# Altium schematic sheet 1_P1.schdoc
size 429 x 307 mm; Symbol: Sheet-Symbol_A3; Device: Sheet-Symbol_A3; Company: 嘉立创EDA; Version: V1.0; Page Size: A3; @Project Name: CASA0021; @Page Count: 1; @Update Date: 2025-02-10; @Create Date: 2025-02-08; @Schematic Name: 主控原理图_V0.2; @Page No: 1; @Page Name: P1; @Board Name: 核心板_V0.2; @Create Time: 18:02:16; @Update Time: 17:02:07; Width: 1655; Height: 1170; Region Start: 1; X Region Count: 6; Y Region Count: 4; Blade Width: 10; Title Block Position: 3
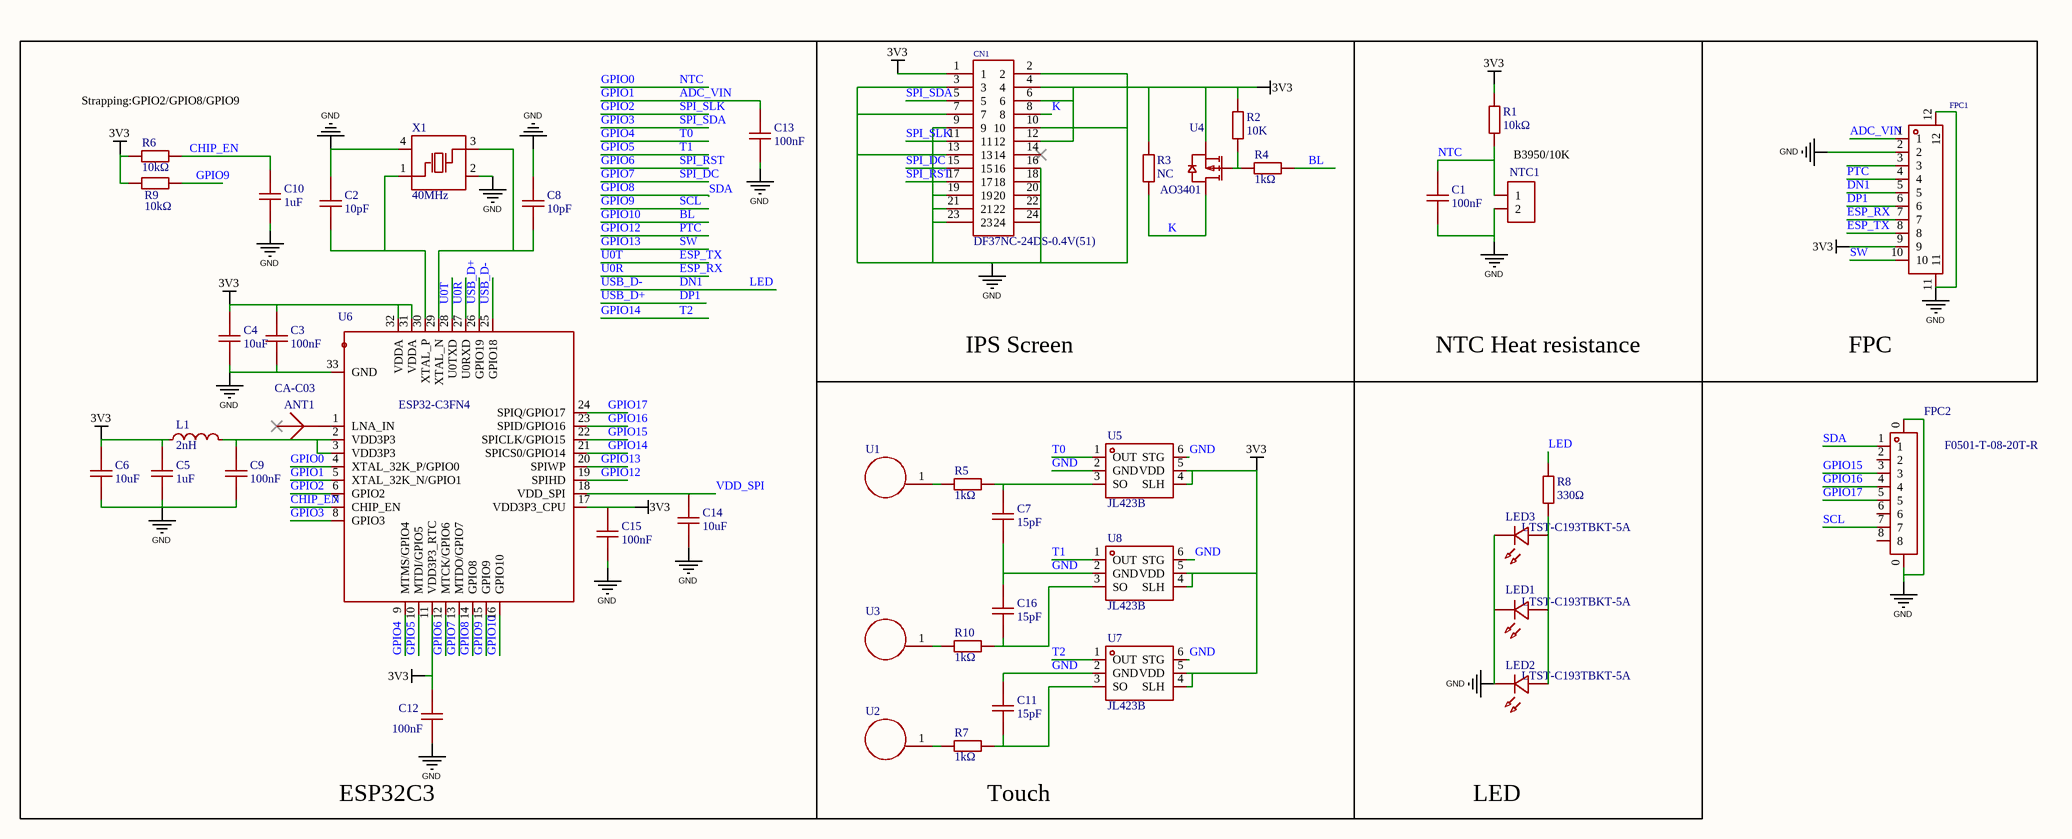
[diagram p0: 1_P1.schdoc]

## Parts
ANT1  CA-C03  [ANT-SMD_CA-C03]
C1  100nF  [C0603]
C2  10pF  [C0603]
C3  100nF  [C0603]
C4  10uF  [C0603]
C5  1uF  [C0603]
C6  10uF  [C0603]
C7  15pF  [C0603]
C8  10pF  [C0603]
C9  100nF  [C0603]
C10  1uF  [C0603]
C11  15pF  [C0603]
C12  100nF  [C0603]
C13  100nF  [C0603]
C14  10uF  [C0603]
C15  100nF  [C0603]
C16  15pF  [C0603]
CN1  DF37NC-24DS-0.4V(51)  [CONN-SMD_DF37NC-24DS-0.4V-51]
FPC1  F0501-T-10-20T-R  [FPC-SMD_F0501-T-10-20T-R]  (value not drawn)
FPC2  F0501-T-08-20T-R  [FPC-SMD_8P-P0.50_L4.4-W9.6]
L1  2nH  [L0603]
LED1  LTST-C193TBKT-5A  [LED0603-RD]
LED2  LTST-C193TBKT-5A  [LED0603-RD]
LED3  LTST-C193TBKT-5A  [LED0603-RD]
NTC1  (no value)  [HDR-TH_2P-P2.54-V-F]
R1  10kΩ  [R0603]
R2  10K  [R0603]
R3  NC  [R0603]
R4  1kΩ  [R0603]
R5  1kΩ  [R0603]
R6  10kΩ  [R0603]
R7  1kΩ  [R0603]
R8  330Ω  [R0603]
R9  10kΩ  [R0603]
R10  1kΩ  [R0603]
U1  F10-10-6.5-0.4P  [TH_F10-10-6.5-0.4P]  (value not drawn)
U2  F10-10-6.5-0.4P  [TH_F10-10-6.5-0.4P]  (value not drawn)
U3  F10-10-6.5-0.4P  [TH_F10-10-6.5-0.4P]  (value not drawn)
U4  AO3401  [SOT-23-3_L2.9-W1.3-P1.90-LS2.4-BR]
U5  JL423B  [SOT-23-6_L2.9-W1.6-P0.95-LS2.8-BL-2]
U6  ESP32-C3FN4  [QFN-32_L5.0-W5.0-P0.50-BL-EP3.7]
U7  JL423B  [SOT-23-6_L2.9-W1.6-P0.95-LS2.8-BL-2]
U8  JL423B  [SOT-23-6_L2.9-W1.6-P0.95-LS2.8-BL-2]
X1  40MHz  [OSC-SMD_4P-L3.2-W2.5-BL_SIT8008BI]

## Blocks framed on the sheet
ESP32C3: ANT1 C2-C6 C8-C10 C12-C15 L1 R6 R9 U6 X1
IPS Screen: CN1 R2-R4 U4
NTC Heat resistance: C1 NTC1 R1
FPC: FPC1
Touch: C7 C11 C16 R5 R7 R10 U1-U3 U5 U7 U8
LED: LED1-LED3 R8

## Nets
3V3: C3.2 C4.2 C5.2 C6.2 C12.2 C15.2 CN1.1 CN1.4 CN1.6 CN1.12 FPC1.9 L1.1 R1.2 R2.1 R3.1 R6.1 R9.1 U4.2(S) U5.4(SLH) U5.5(VDD) U6.11(VDD3P3_RTC) U6.17(VDD3P3_CPU) U6.31(VDDA) U6.32(VDDA) U7.4(SLH) U7.5(VDD) U8.4(SLH) U8.5(VDD)
GND: C1.1 C2.2 C3.1 C4.1 C5.1 C6.1 C7.1 C8.2 C9.1 C10.1 C11.2 C12.1 C13.2 C14.1 C15.1 C16.2 CN1.2 CN1.3 CN1.7 CN1.9 CN1.10 CN1.13 CN1.16 CN1.18 CN1.19 CN1.20 CN1.21 CN1.22 CN1.23 CN1.24 FPC1.2 FPC1.11 FPC1.12 FPC2.0 LED1.1(C) LED2.1(C) LED3.1(C) NTC1.2 U5.2(GND) U5.6(STG) U6.33(GND) U7.2(GND) U7.6(STG) U8.2(GND) U8.6(STG) X1.2(GND) X1.4(GND)
ADC_VIN: C13.1 FPC1.1 U6.5(XTAL_32K_N/GPIO1)  [also labelled GPIO1]
BL: R4.1 U6.16(GPIO10)  [also labelled GPIO10]
CHIP_EN: C10.2 R6.2 U6.7(CHIP_EN)
DN1: FPC1.5 R8.1 U6.25(GPIO18)  [also labelled LED, USB_D-]
DP1: FPC1.6 U6.26(GPIO19)  [also labelled USB_D+]
ESP_RX: FPC1.7 U6.27(U0RXD)  [also labelled U0R]
ESP_TX: FPC1.8 U6.28(U0TXD)  [also labelled U0T]
GPIO0: C1.2 NTC1.1 R1.1 U6.4(XTAL_32K_P/GPIO0)  [also labelled NTC]
GPIO2: CN1.11 U6.6(GPIO2)  [also labelled SPI_SLK]
GPIO3: CN1.5 U6.8(GPIO3)  [also labelled SPI_SDA]
GPIO4: U5.1(OUT) U6.9(MTMS/GPIO4)  [also labelled T0]
GPIO5: U6.10(MTDI/GPIO5) U8.1(OUT)  [also labelled T1]
GPIO6: CN1.17 U6.12(MTCK/GPIO6)  [also labelled SPI_RST]
GPIO7: CN1.15 U6.13(MTDO/GPIO7)  [also labelled SPI_DC]
GPIO8: FPC2.1 U6.14(GPIO8)  [also labelled SDA]
GPIO9: FPC2.7 R9.2 U6.15(GPIO9)  [also labelled SCL]
GPIO12: FPC1.4 U6.19(SPIHD)  [also labelled PTC]
GPIO13: FPC1.10 U6.20(SPIWP)  [also labelled SW]
GPIO14: U6.21(SPICS0/GPIO14) U7.1(OUT)  [also labelled T2]
GPIO15: FPC2.3 U6.22(SPICLK/GPIO15)
GPIO16: FPC2.4 U6.23(SPID/GPIO16)
GPIO17: FPC2.5 U6.24(SPIQ/GPIO17)
K: CN1.8 R3.2 U4.3(D)
VDD_SPI: C14.2 U6.18(VDD_SPI)
NetANT1_2: ANT1.2(ANT) U6.1(LNA_IN)
NetC2_1: C2.1 U6.30(XTAL_P) X1.1(OSC1)
NetC7_2: C7.2 R5.2 U5.3(SO)
NetC8_1: C8.1 U6.29(XTAL_N) X1.3(OSC2)
NetC9_2: C9.2 L1.2 U6.2(VDD3P3) U6.3(VDD3P3)
NetC11_1: C11.1 R7.2 U7.3(SO)
NetC16_1: C16.1 R10.2 U8.3(SO)
NetLED1_2: LED1.2(A) LED2.2(A) LED3.2(A) R8.2
NetR2_2: R2.2 R4.2 U4.1(G)
NetR5_1: R5.1 U1.1
NetR7_1: R7.1 U2.1
NetR10_1: R10.1 U3.1

Not connected (* = marked no-connect by the designer): ANT1 1*; CN1 14*; FPC1 3; FPC2 2 6 8

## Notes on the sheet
- Strapping:GPIO2/GPIO8/GPIO9
- B3950/10K

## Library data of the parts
ANT1 = CA-C03: Add into BOM: yes
C1 C13 = CGA0603X7R104K500JT: Manufacturer: HRE(芯声); Symbol: CapAcitance; Add into BOM: yes; Tolerance: ±10%; Voltage Rated: 50V; Temperature Coefficient: X7R
C2 = CC0603KRNPO9BN100: Manufacturer: YAGEO(国巨); Symbol: CapAcitance; Add into BOM: yes; Tolerance: ±10%; Voltage Rated: 50V; Temperature Coefficient: NP0
C3 C9 C12 C15 = CC0603KRX7R9BB104: Manufacturer: YAGEO(国巨); Symbol: CapAcitance; Add into BOM: yes; Tolerance: ±10%; Voltage Rated: 50V; Temperature Coefficient: X7R
C4 C6 C14 = CL10A106KP8NNNC: Manufacturer: SAMSUNG(三星); Symbol: CapAcitance; Add into BOM: yes; Tolerance: ±10%; Voltage Rated: 10V; Temperature Coefficient: X5R
C5 C10 = CL10A105KA8NNNC: Manufacturer: SAMSUNG(三星); Symbol: CapAcitance; Add into BOM: yes; Tolerance: ±10%; Voltage Rated: 25V; Temperature Coefficient: X5R
C7 C11 C16 = CC0603JRNPO9BN150: Manufacturer: YAGEO(国巨); Symbol: CapAcitance; Add into BOM: yes; Tolerance: ±5%; Voltage Rated: 50V; Temperature Coefficient: NP0
C8 = CC0603FRNPO9BN100: Manufacturer: YAGEO(国巨); Symbol: CapAcitance; Add into BOM: yes; Tolerance: ±1%; Voltage Rated: 50V; Temperature Coefficient: NP0
CN1 = DF37NC-24DS-0.4V(51): Manufacturer: HRS(广濑); Add into BOM: yes; Pitch: 0.4mm; Gender: 母; Current Rating (Max): 300mA
FPC1 = F0501-T-10-20T-R: Manufacturer: XFCN(兴飞); Add into BOM: yes; Pitch: 0.5mm; Number of Contacts: 10P; Locking Feature: 抽屉式
FPC2 = F0501-T-08-20T-R: Manufacturer: XFCN(兴飞); Add into BOM: yes; Locking Feature: 抽屉式; Number of Contacts: 8P; Pitch: 0.5mm
L1 = SDCL1608C2N0STDF: Manufacturer: Sunlord(顺络); Symbol: SDCL1005C10NJTDFM01; Add into BOM: yes
LED1-LED3 = LTST-C193TBKT-5A: Manufacturer: LITEON(光宝); Symbol: LED_B; Convert to PCB: yes; Emitted Color: 蓝色; Forward Voltage (VF): 2.8V; Power Dissipation: 76mW; Forward Current: 5mA; Dominant Wavelength: 465nm~475nm; Peak Wavelength: 468nm; Lens Color: 无色透明透镜; Luminous Intensity: 15mcd; Viewing Angle: 130°
NTC1 = HDR-F_2.54_1x2P: Manufacturer: BOOMELE(博穆精密); Manufacturer Part: 2.54-1*2P母; Symbol: Header-Female-2.54_1x2; Convert to PCB: yes
R1 R6 R9 = 0603WAF1002T5E: Manufacturer: UNI-ROYAL(厚声); Symbol: 电阻; Add into BOM: yes; Tolerance: ±1%; Power(Watts): 100mW; Overload Voltage (Max): 75V; Temperature Coefficient: ±100ppm/℃
R2 R3 = Res_0402: Symbol: 电阻; Convert to PCB: yes; Add into BOM: no
R4 R5 R7 R10 = 0603WAF1001T5E: Manufacturer: UNI-ROYAL(厚声); Symbol: 电阻; Add into BOM: yes; Tolerance: ±1%; Power(Watts): 100mW; Overload Voltage (Max): 75V; Temperature Coefficient: ±100ppm/℃
R8 = 0603WAF3300T5E: Manufacturer: UNI-ROYAL(厚声); Symbol: 电阻; Add into BOM: yes; Tolerance: ±1%; Power(Watts): 100mW; Overload Voltage (Max): 75V; Temperature Coefficient: ±100ppm/℃
U1-U3 = F10-10-6.5-0.4P: Manufacturer: Sam&wing(芯网); Symbol: 触摸弹簧 H10.0MM; Add into BOM: yes
U4 = AO3401_1: Manufacturer: FOSAN(富信); Symbol: AO3401A_C5122001; Add into BOM: yes; Drain Source Voltage (Vdss): 30V; Continuous Drain Current (Id): 4.4A
U5 U7 U8 = JL423B: Add into BOM: yes
U6 = ESP32-C3FN4: Manufacturer: ESPRESSIF(乐鑫); Add into BOM: yes
X1 = X322540MPB4SI: Manufacturer: YXC(扬兴晶振); Add into BOM: yes; Crystal Type: 贴片无源晶振; Frequency Tolerance: ±10ppm; Frequency Stability: ±30ppm; Load Capacitance: 15pF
